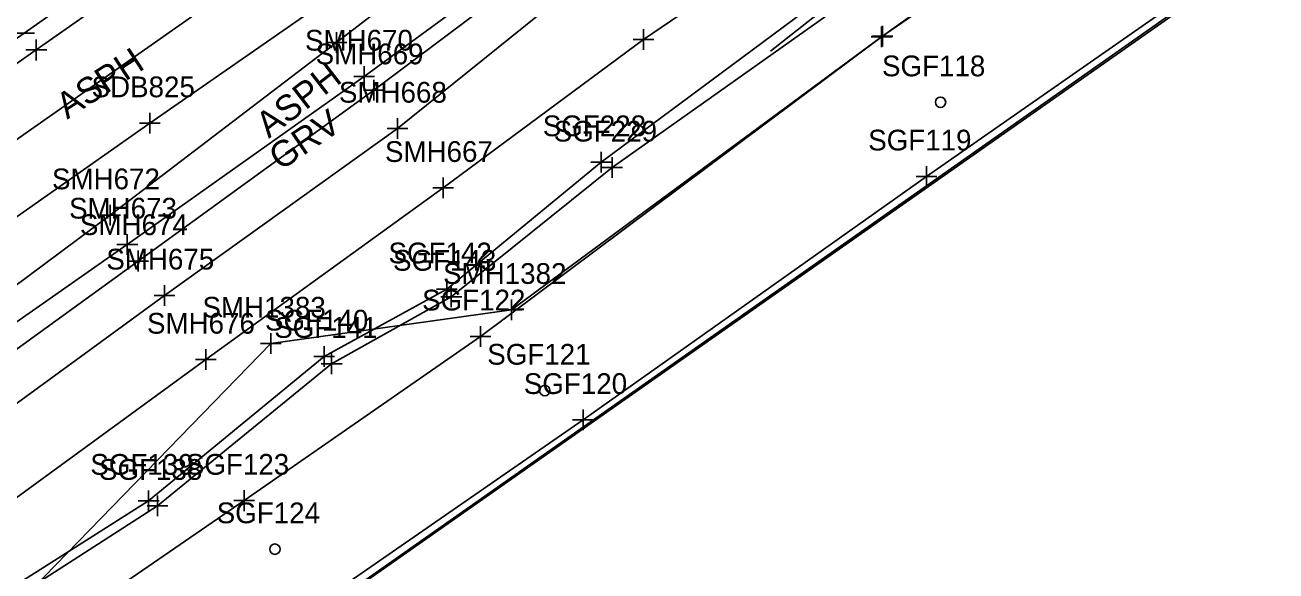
# Model space of a CAD drawing. Extents: x 941041 to 969446, y 397014 to 416764.
# Drawn here: x 952807.2 to 953048.5, y 403770.9 to 403876.1 of the extents above; entities that cross this region are included whole.
import ezdxf

# ---------------------------------------------------------------- set-up
doc = ezdxf.new("R2010")
doc.units = 0
for name, color, linetype in [('SURVEY - DRAINAGE - Area Shapes', 7, 'Continuous'), ('SURVEY - DRAINAGE - Area Shapes Text', 7, 'Continuous'), ('SURVEY - DTM - Breaklines', 7, 'Continuous'), ('SURVEY - DTM - Breaklines - Points - Locators', 7, 'Continuous'), ('SURVEY - DTM - Breaklines - Points - Numbers', 7, 'Continuous'), ('SURVEY - DTM - Spot Points - Locators', 7, 'Continuous'), ('SURVEY - DTM - Spot Points - Point Numbers', 7, 'Continuous'), ('SURVEY - DTM GRAPHICS - Boundary Line', 7, 'Continuous'), ('SURVEY - NON-TRANSPORTATION - Features', 7, 'Continuous'), ('SURVEY - NON-TRANSPORTATION - Features - Points - Locators', 7, 'Continuous'), ('SURVEY - NON-TRANSPORTATION - Features - Points - Numbers', 7, 'Continuous'), ('SURVEY - PROPERTY - ROW Lines', 7, 'Continuous'), ('SURVEY - TRANSPORTATION - Features', 7, 'Continuous'), ('SURVEY - TRANSPORTATION - Features - Points - Locators', 7, 'Continuous'), ('SURVEY - TRANSPORTATION - Features - Points - Numbers', 7, 'Continuous'), ('SURVEY - TRANSPORTATION - Features Text', 7, 'Continuous'), ('SURVEY - TRANSPORTATION - Roads', 7, 'Continuous'), ('SURVEY - TRANSPORTATION - Roads - Points - Locators', 7, 'Continuous'), ('SURVEY - TRANSPORTATION - Roads - Points - Numbers', 7, 'Continuous'), ('SURVEY - VEGETATION - Features - Points - Locators', 7, 'Continuous'), ('SURVEY - VEGETATION - Features - Points - Numbers', 7, 'Continuous'), ('SURVEY - VEGETATION - Features with Text', 7, 'Continuous')]:
    doc.layers.add(name, color=color, linetype=linetype)

msp = doc.modelspace()

# ---------------------------------------------------------------- linework, layer by layer
at = {"layer": 'SURVEY - DRAINAGE - Area Shapes'}
msp.add_lwpolyline([(954050.98, 404130.56), (953837.45, 404341.16), (953706.36, 404460.47), (953686.21, 404471.93), (953450.22, 404306.36), (952524.78, 403657.05)], dxfattribs=at)
at = {"layer": 'SURVEY - DRAINAGE - Area Shapes Text'}
msp.add_line((952980.44, 403894.29), (952950.95, 403871.09), dxfattribs=at)
at = {"layer": 'SURVEY - DTM - Breaklines'}
for points in [[(953434.32, 404202.37), (953401.29, 404167.95), (953352.13, 404141.91), (953317.24, 404119.57), (953259.72, 404086.89), (953210.13, 404050.08), (953163.23, 404016.46), (953123.6, 403992.48), (953068.74, 403952.48), (953031.33, 403929.82), (952972.85, 403890.17), (952918.35, 403849.7), (952888.56, 403825.19)], [(953434.75, 404201.6), (953401.96, 404167.11), (953353.13, 404140.03), (953317.67, 404118.32), (953260.82, 404085.35), (953210.55, 404048.65), (953163.98, 404014.33), (953125.14, 403990.61), (953070.13, 403951.17), (953033.07, 403927.99), (952975.29, 403887.54), (952920.44, 403848.67)], [(953398.65, 404176.28), (953348.77, 404147.35), (953294.78, 404123.47), (953240.01, 404086.89), (953186.29, 404052.29), (953136.63, 404016.77), (953088.35, 403985.15), (953030.11, 403949.56), (952979.78, 403909.56), (952926.5, 403873.35)], [(953256.01, 404071.77), (953222.78, 404046.68), (953161.65, 404006.17), (953130.63, 403984.73), (953077.73, 403948.74), (953016.96, 403905.76), (952972.55, 403873.99), (952895.04, 403816.11), (952849.49, 403784.45), (952806.1, 403754.66), (952758.51, 403717.61), (952745.6, 403709.26)], [(952447.47, 403587.87), (952492.12, 403619.04), (952535.18, 403649.21), (952579.12, 403679.85), (952622.63, 403710.51), (952664.16, 403739.7), (952705.31, 403768.85), (952749.94, 403799.92), (952791.79, 403829.44), (952831.3, 403857.21), (952872.52, 403885.88), (952913.94, 403914.99), (952957.12, 403945.2), (952999.49, 403974.88), (953016.81, 403987.05)], [(952917.54, 403887.23), (952879.05, 403856.17), (952834.15, 403824), (952789.53, 403791.48), (952743.17, 403759.1), (952699.51, 403726.33), (952652.89, 403694.34), (952605.64, 403661.7), (952558.8, 403631.47), (952496.14, 403581.58), (952474.11, 403564.31), (952441.21, 403533.58), (952397.8, 403490.51), (952380.05, 403468.98)], [(952926.5, 403873.35), (952887.88, 403844.74), (952842.1, 403811.64), (952797.54, 403779.23), (952751.48, 403746.32), (952706.83, 403715.15), (952659.98, 403683.17), (952615.08, 403648.75)], [(952737.07, 403722.49), (952770.44, 403743.37), (952832.79, 403783.46), (952866.36, 403810.83), (952889.43, 403823.77), (952920.44, 403848.67)], [(952736.12, 403724.5), (952770.09, 403745.77), (952831.07, 403784.44), (952864.92, 403812.24), (952888.56, 403825.19)]]:
    msp.add_lwpolyline(points, dxfattribs=at)
at = {"layer": 'SURVEY - DTM - Breaklines - Points - Locators'}
for p, q in [((952926.5, 403875.35), (952926.5, 403871.35)), ((952974.55, 403873.99), (952970.55, 403873.99)), ((952972.55, 403875.99), (952972.55, 403871.99)), ((952928.5, 403873.35), (952924.5, 403873.35)), ((952833.3, 403857.21), (952829.3, 403857.21)), ((952831.3, 403859.21), (952831.3, 403855.21)), ((952879.05, 403858.17), (952879.05, 403854.17)), ((952881.05, 403856.17), (952877.05, 403856.17)), ((952918.35, 403851.7), (952918.35, 403847.7)), ((952920.44, 403850.67), (952920.44, 403846.67)), ((952920.35, 403849.7), (952916.35, 403849.7)), ((952922.44, 403848.67), (952918.44, 403848.67)), ((952887.88, 403846.74), (952887.88, 403842.74)), ((952889.88, 403844.74), (952885.88, 403844.74)), ((952834.15, 403826), (952834.15, 403822)), ((952888.56, 403827.19), (952888.56, 403823.19)), ((952889.43, 403825.77), (952889.43, 403821.77)), ((952836.15, 403824), (952832.15, 403824)), ((952890.56, 403825.19), (952886.56, 403825.19)), ((952891.43, 403823.77), (952887.43, 403823.77)), ((952897.04, 403816.11), (952893.04, 403816.11)), ((952895.04, 403818.11), (952895.04, 403814.11)), ((952842.1, 403813.64), (952842.1, 403809.64)), ((952864.92, 403814.24), (952864.92, 403810.24)), ((952844.1, 403811.64), (952840.1, 403811.64)), ((952866.92, 403812.24), (952862.92, 403812.24)), ((952866.36, 403812.83), (952866.36, 403808.83)), ((952868.36, 403810.83), (952864.36, 403810.83)), ((952831.07, 403786.44), (952831.07, 403782.44)), ((952832.79, 403785.46), (952832.79, 403781.46)), ((952849.49, 403786.45), (952849.49, 403782.45)), ((952833.07, 403784.44), (952829.07, 403784.44)), ((952834.79, 403783.46), (952830.79, 403783.46)), ((952851.49, 403784.45), (952847.49, 403784.45))]:
    msp.add_line(p, q, dxfattribs=at)
at = {"layer": 'SURVEY - DTM - Spot Points - Locators'}
for centre in [(952983.77, 403861.25), (952907.45, 403805.66), (952855.43, 403775.1)]:
    msp.add_circle(centre, 1, dxfattribs=at)
at = {"layer": 'SURVEY - DTM GRAPHICS - Boundary Line'}
msp.add_lwpolyline([(952613.11, 403589.47), (952670.27, 403628.77), (952767.62, 403696.96), (952768.86, 403698.28), (952816, 403731.06), (952852.21, 403756.69), (952914.83, 403800.01), (952981.07, 403846.95), (953038.17, 403886.75), (953150.23, 403964.85), (953203.83, 404002.68), (953229.9, 404020.9), (953265.94, 404045.81)], dxfattribs=at)
at = {"layer": 'SURVEY - NON-TRANSPORTATION - Features'}
msp.add_lwpolyline([(953229.9, 404020.9), (953203.83, 404002.68), (953150.23, 403964.85), (953088.48, 403922.23), (953038.17, 403886.75), (952981.07, 403846.95), (952914.83, 403800.01), (952852.21, 403756.69), (952816, 403731.06), (952768.86, 403698.28), (952767.62, 403696.96)], dxfattribs=at)
at = {"layer": 'SURVEY - NON-TRANSPORTATION - Features - Points - Locators'}
for p, q in [((952981.07, 403848.95), (952981.07, 403844.95)), ((952983.07, 403846.95), (952979.07, 403846.95)), ((952914.83, 403802.01), (952914.83, 403798.01)), ((952916.83, 403800.01), (952912.83, 403800.01))]:
    msp.add_line(p, q, dxfattribs=at)
at = {"layer": 'SURVEY - PROPERTY - ROW Lines'}
msp.add_line((952368.92, 403415.42), (953970.44, 404538.71), dxfattribs=at)
at = {"layer": 'SURVEY - TRANSPORTATION - Features'}
msp.add_lwpolyline([(952913.84, 403893.14), (952874.52, 403863.56), (952829.06, 403830.64), (952784.66, 403798.47), (952739.16, 403766), (952693.74, 403734.13), (952648.44, 403702.25), (952600.48, 403670.02), (952552.63, 403637.1), (952490.83, 403589.2), (952470.74, 403572.76), (952463.7, 403566.84)], dxfattribs=at)
at = {"layer": 'SURVEY - TRANSPORTATION - Features - Points - Locators'}
for p, q in [((952874.52, 403865.56), (952874.52, 403861.56)), ((952876.52, 403863.56), (952872.52, 403863.56)), ((952831.06, 403830.64), (952827.06, 403830.64)), ((952829.06, 403832.64), (952829.06, 403828.64))]:
    msp.add_line(p, q, dxfattribs=at)
at = {"layer": 'SURVEY - TRANSPORTATION - Roads'}
for points in [[(953046.11, 404041.98), (952997.22, 404007.75), (952947.55, 403972.95), (952899.56, 403939.37), (952853.51, 403907.24), (952807.05, 403874.59), (952761.33, 403842.53), (952717, 403811.35), (952670.69, 403778.86), (952625.22, 403746.95), (952579.91, 403715.1)], [(953047.38, 404038.13), (952999.67, 404004.66), (952947.65, 403968.16), (952902.02, 403936.14), (952856.05, 403904.05), (952809.41, 403871.32), (952763.34, 403839.04), (952719.12, 403808.03), (952671.74, 403774.84), (952627.47, 403743.75), (952581.75, 403711.66)], [(952905.89, 403902.49), (952867.28, 403872.76), (952823.67, 403839.47), (952779.24, 403806.48), (952734.21, 403774.52), (952688.26, 403742.16), (952642.64, 403710.46), (952595.33, 403677.1), (952547.64, 403643.77), (952484.32, 403598.74), (952462.03, 403582.12), (952455.35, 403576.86)], [(952912.48, 403895.47), (952872.63, 403866.2), (952826.96, 403833.82), (952782.17, 403802.55), (952736.34, 403770.63), (952690.18, 403738.66), (952644.94, 403707.09), (952597.62, 403673.8), (952550.6, 403640.2), (952487.73, 403593.63), (952466.12, 403577.04), (952459.67, 403571.86)]]:
    msp.add_lwpolyline(points, dxfattribs=at)
at = {"layer": 'SURVEY - TRANSPORTATION - Roads - Points - Locators'}
for p, q in [((952809.05, 403874.59), (952805.05, 403874.59)), ((952867.28, 403874.76), (952867.28, 403870.76)), ((952809.41, 403873.32), (952809.41, 403869.32)), ((952869.28, 403872.76), (952865.28, 403872.76)), ((952811.41, 403871.32), (952807.41, 403871.32)), ((952872.63, 403868.2), (952872.63, 403864.2)), ((952874.63, 403866.2), (952870.63, 403866.2)), ((952823.67, 403841.47), (952823.67, 403837.47)), ((952825.67, 403839.47), (952821.67, 403839.47)), ((952826.96, 403835.82), (952826.96, 403831.82)), ((952828.96, 403833.82), (952824.96, 403833.82))]:
    msp.add_line(p, q, dxfattribs=at)
at = {"layer": 'SURVEY - VEGETATION - Features - Points - Locators'}
for p, q in [((952972.41, 403875.85), (952972.41, 403871.85)), ((952974.41, 403873.85), (952970.41, 403873.85)), ((952903.03, 403821.23), (952899.03, 403821.23)), ((952901.03, 403823.23), (952901.03, 403819.23)), ((952854.64, 403816.73), (952854.64, 403812.73)), ((952856.64, 403814.73), (952852.64, 403814.73))]:
    msp.add_line(p, q, dxfattribs=at)
at = {"layer": 'SURVEY - VEGETATION - Features with Text'}
for points in [[(953978, 404545.36), (952376.77, 403420.76)], [(952615.41, 403645.7), (952663.71, 403647.1), (952767.16, 403724.79), (952854.64, 403814.73), (952901.03, 403821.23), (952972.41, 403873.85), (953072.36, 403942.71), (953151.12, 403998.66), (953210.95, 404036), (953255.08, 404074.19), (953321.18, 404112.82), (953394.86, 404155.77), (953420.13, 404180.6), (953476.58, 404225.47), (953504.82, 404236.22), (953494.06, 404250.8)]]:
    msp.add_lwpolyline(points, dxfattribs=at)

# ---------------------------------------------------------------- texts
at = {"layer": 'SURVEY - DTM - Breaklines - Points - Numbers'}
for s, p in [('SDB825', (952820.06, 403862.21)), ('SMH668', (952867.76, 403861.17)), ('SGF228', (952907.07, 403854.7)), ('SGF229', (952909.18, 403853.67)), ('SMH667', (952876.64, 403849.74)), ('SMH675', (952822.91, 403829)), ('SGF142', (952877.32, 403830.19)), ('SGF143', (952878.19, 403828.77)), ('SGF122', (952883.8, 403821.11)), ('SGF140', (952853.5, 403817.24)), ('SMH676', (952830.75, 403816.64)), ('SGF141', (952855.28, 403815.83)), ('SGF139', (952819.82, 403789.44)), ('SGF138', (952821.5, 403788.46)), ('SGF123', (952838.25, 403789.45))]:
    msp.add_text(s, height=4, dxfattribs=at).set_placement(p)
at = {"layer": 'SURVEY - DTM - Spot Points - Point Numbers'}
for s, p in [('SGF118', (952972.48, 403866.25)), ('SGF121', (952896.36, 403810.66)), ('SGF124', (952844.19, 403780.1))]:
    msp.add_text(s, height=4, dxfattribs=at).set_placement(p)
at = {"layer": 'SURVEY - NON-TRANSPORTATION - Features - Points - Numbers'}
for s, p in [('SGF119', (952969.82, 403851.95)), ('SGF120', (952903.41, 403805.01))]:
    msp.add_text(s, height=4, dxfattribs=at).set_placement(p)
at = {"layer": 'SURVEY - TRANSPORTATION - Features - Points - Numbers'}
for s, p in [('SMH669', (952863.27, 403868.56)), ('SMH674', (952817.82, 403835.64))]:
    msp.add_text(s, height=4, dxfattribs=at).set_placement(p)
at = {"layer": 'SURVEY - TRANSPORTATION - Features Text'}
for s, rotation, p in [('ASPH', 33.2317, (952815.36, 403857.88)), ('ASPH', 37.5686, (952854.23, 403854.19)), ('GRV', 33.8453, (952856.48, 403847.95))]:
    msp.add_text(s, height=5, rotation=rotation, dxfattribs=at).set_placement(p)
at = {"layer": 'SURVEY - TRANSPORTATION - Roads - Points - Numbers'}
for s, p in [('SMH670', (952861.22, 403871.2)), ('SMH672', (952812.43, 403844.47)), ('SMH673', (952815.72, 403838.82))]:
    msp.add_text(s, height=4, dxfattribs=at).set_placement(p)
at = {"layer": 'SURVEY - VEGETATION - Features - Points - Numbers'}
for s, p in [('SMH1382', (952887.84, 403826.23)), ('SMH1383', (952841.44, 403819.73))]:
    msp.add_text(s, height=4, dxfattribs=at).set_placement(p)

doc.saveas('drawing.dxf')
